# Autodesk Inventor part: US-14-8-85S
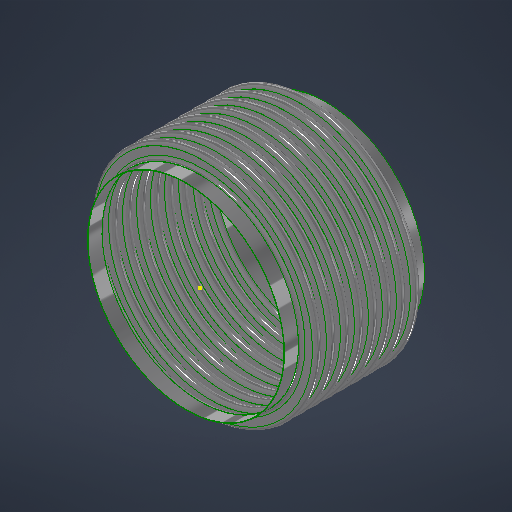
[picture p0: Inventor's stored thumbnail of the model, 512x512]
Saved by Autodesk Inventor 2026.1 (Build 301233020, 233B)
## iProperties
Category: 20 GA (0.036 THICK)
RuleStatus: InUse
Created: 2026-07
Part Number: US-14-8-85S
Project: =STOCK BELLOWS: <Stock Number><SFILL>
Material: ASTM A240-304
Description: =STOCK BELLOWS: <Stock Number>, <SID_> I.D., <SOD_> O.D., <SPLY_> PLY, <Category>, <SNET_CONS> CONS.<PITCH_><STANGENT_> TANGENT<SFILL>
Document SubType Name: Sheet Metal
Designer: LC
Stock Number: U.S-I4-8-85S
Surface Area: 659.127 cm^2
Volume: 56.61 cm^3
Sheet Metal Rule: Default
Appearance: STAINLESS STEEL
NET_TUBE: 3.428
COUNTER: 1.500
PBAR: 1.214
PSET: 5.356
PLY: 2
CONS: 2
THK: 0.036
ID: 4.500
OD: 5.500
CONS_: 2
TANGENT: 0.500
PITCH: 0.375
BELLOWS_UPSET: 0.000
NET_CONS: 2
S_CONS: 0
Description_Units: 0
ID_M: 114.30 mm
OD_M: 139.70 mm
THK_M: 0.91 mm
ID_U: 4.500 in
OD_U: 5.500 in
THK_U: 0.036 in
TANGENT2: 0.500
d79: 1.000
d82: 1.000
d83: 26.000
d84: 24.000
d80: 2.571
d81: 10
SID: 2.375
SCONS_: 8
SPITCH: 0.250
SBELLOWS_UPSET: 0.000
SNET_CONS: 8
SS_CONS: 0
SCONS: 8
d174: 8
d177: 0.018
d178: 2.375
d179: 3.000
d180: 0.375
d181: 1.000
d182: 0.000
d190: 8
d191: 1
d192: 1
d193: 8
d194: 0
PART_NUMBER: U.S-I4-8-85S
PRESSURE: 85
SIZE: 14.00
STANGENT_: 1.000
d214: 8
d217: 0.030
d218: 6.625
d219: 8.125
d220: 0.500
d221: 1.000
d222: 0.000
d230: 8
d231: 1
d232: 1
d233: 8
d234: 0
STANGENT: 4.000
SPLY_: 1
STHK_: 0.036
SID_: 14.000
SOD_: 16.125
SPITCH_: 1.000
STANGENT__: 1.000
SBELLOWS_UPSET_: 0.000
SDIFF_TAN: 1.000
TAN_TO_TAN: 0.750 in
d252: 2
d275: 2
d287: 0.050
d289: 0.500
d290: 0.000
d263: 2
d265: 1
d268: 2
d269: 0
d286: 2
d288: 1
d291: 2
d292: 0
SOD_NECK: 14 1/16
CFILL: .
SFILL: .
PITCH_: =, <SPITCH_> PITCH,
SREROLL: 0.750
MATTABLE: 20 GA (0.036 THICK)
MESH: ,
CSECT: 2
Author: LC
Keywords: 20 GA (0.036 THICK)
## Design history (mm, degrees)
sketch "Sketch2"
  geometry: L1 (0, -183.595)-(0, 600.956) reference; L2 (58.979, 0)-(57.15, 0); L3 (60.446, -1.467)-(66.554, -1.467); L4 (60.446, -3.296)-(66.554, -3.296); L5 (66.554, -8.058)-(60.446, -8.058); L6 (66.554, -6.229)-(60.446, -6.229); L7 (58.979, -9.525)-(57.15, -9.525); L8 (60.446, 0)-(60.446, -9.525); L9 (66.554, -4.762)-(69.85, -4.763); L10 (57.15, 0)-(57.15, -9.525); L11 (20.376, 102.841)-(20.376, 101.926); L12 (58.262, 488.877)-(58.262, 349.177); L13 (58.262, 479.352)-(58.262, 339.652); L14 (93.133, -58.817)-(93.133, -71.517); L15 (118.746, -66.401)-(118.746, -66.401); L16 (66.554, -6.229)-(66.554, -8.058); L17 (60.446, -6.229)-(60.446, -8.058); L18 (60.446, -7.144)-(66.554, -7.144); L19 (69.85, 0)-(69.85, -9.525); L20 (-66.554, -6.229)-(-66.554, -8.058); L21 (-66.554, -1.467)-(-60.446, -1.467); L22 (-66.554, -3.296)-(-60.446, -3.296); L23 (-60.446, -6.229)-(-66.554, -6.229); L24 (-66.554, -7.144)-(-60.446, -7.144); L25 (-60.446, -8.058)-(-66.554, -8.058); L26 (-60.446, -6.229)-(-60.446, -8.058); L27 (-57.15, -2.522)-(-57.15, -12.047); L28 (-60.446, -4.763)-(-57.15, -4.763); L29 (-66.554, 3.828)-(-66.554, -9.525); L30 (-68.021, 0)-(-69.85, 0); L31 (-69.85, 0)-(-69.85, -9.525); L32 (-68.021, -9.525)-(-69.85, -9.525); A1 r 1.467 centre (60.446, 0) between (58.979, 0) and (60.446, -1.467); A2 r 3.296 centre (60.446, 0) between (57.15, 0) and (60.446, -3.296); A3 r 3.296 centre (66.554, -4.762) between (66.554, -8.058) and (66.554, -1.467); A4 r 1.467 centre (66.554, -4.762) between (66.554, -6.229) and (66.554, -3.296); A5 r 1.467 centre (60.446, -9.525) between (60.446, -8.058) and (58.979, -9.525); A6 r 3.296 centre (60.446, -9.525) between (60.446, -6.229) and (57.15, -9.525); A7 r 2.381 centre (66.554, -4.762) between (66.554, -7.144) and (68.936, -4.762); A8 r 2.381 centre (60.446, -9.525) between (60.446, -7.144) and (58.064, -9.525); A9 r 1.467 centre (-66.554, -9.525) between (-66.554, -8.058) and (-68.021, -9.525); A10 r 1.467 centre (-60.446, -4.763) between (-60.446, -6.229) and (-60.446, -3.296); A11 r 2.381 centre (-60.446, -4.763) between (-60.446, -7.144) and (-58.064, -4.763); A12 r 3.296 centre (-60.446, -4.763) between (-60.446, -8.058) and (-60.446, -1.467); A13 r 2.381 centre (-66.554, -9.525) between (-66.554, -7.144) and (-68.936, -9.525); A14 r 3.296 centre (-66.554, -9.525) between (-66.554, -6.229) and (-69.85, -9.525); A15 r 1.467 centre (-66.554, 0) between (-68.021, 0) and (-66.554, -1.467); A16 r 3.296 centre (-66.554, 0) between (-69.85, 0) and (-66.554, -3.296); 10 further points
  constraints: 62 end point, 38 point on circle, 20 tangent, 16 centre point, 12 parallel, 9 midpoint, 7 vertical, 6 coincident, 6 concentric, 6 point on line, 4 equal radius, 4 perpendicular, 3 horizontal, 1 collinear, 1 horizontal alignment, 10 other
  dimensions: "THK" = 0.9144 distance of L11.start L11.end; "ID" = 114.3 distance of L11.end point (20.376, -12.374); "OD" = 139.7 distance of L12.start L12.end; "PITCH" = 9.525 distance of L12.start L13.start; "TANGENT" = 12.7 distance of L14.start L14.end; "BELLOWS_UPSET" = 0 distance of L15.start L15.end; "d43" = 114.3 diameter of L10 L1 (= ID); "d44" = 139.7 diameter of L9.end L1 (= OD); "d45" = 1.8288 distance between parallel lines of L5 L6 (computed from THK, PLY); "d46" = 3.29565 radius of A3 (computed from PITCH, THK, PLY); "UPSET_PITCH" = 9.525 distance of L2.end L7.end (derived); "SIDEWALL_ANGLE" = 0 deg angle of L3 L9 (derived); "CON_GAP" = 2.9337 distance of point (60.446, -6.229) point (60.446, -3.296) (derived); "TAN1" = 3.74046 dimension on A8 (derived); "TAN2" = 3.74046 dimension on A7 (derived); "LEG1" = 6.1087 distance of L18.start L18.end (derived); "d278" = 1.8288 distance between parallel lines of L25 L23 (derived); "d279" = 3.29565 radius of A12 (derived); "d280" = 9.525 distance of L30.end L31.end (derived); "d281" = 360 deg dimension on L21 L28 (derived); "d282" = 2.9337 distance of point (-66.554, -6.229) point (-66.554, -3.296) (derived); "d283" = 3.74046 dimension on A13 (derived); "d284" = 3.74046 dimension on A11 (derived); "d285" = 6.1087 distance of L24.start L24.end (derived); "d293" = 114.3 diameter of L27 L1 (derived); "d294" = 139.7 diameter of L31 L1 (derived)
  node "Sketch Rectangular Pattern1" dims "d31" = 25.4, "ID" = 114.3
  node "Sketch Rectangular Pattern2" dims "d39" = 25.4, "PITCH" = 9.525
revolve "CONS" stored, may be unused: angle "d48" = 90 deg
node "BELLOW MIDPLANE"
pattern_linear "Rectangular Pattern2" dims "d52" = 9.525 (= UPSET_PITCH)
sketch "Sketch5"
  geometry: C1 r 58.979 at (0, 0) reference; C2 r 57.15 at (0, 0) reference
extrude "TANGENT" new body sketch "Sketch5" distance "d53" = 12.7 (= TANGENT); taper "d54" = 0 deg
revolve "SAMETAN" stored, may be unused: angle "d65" = 90 deg
revolve "DIFFTAN" stored, may be unused: angle "d70" = 90 deg
sketch "Sketch9"
  geometry: L1 (58.391, 0)-(-58.391, 0) reference; L2 (0, -17.78)-(0, 17.78) reference; L3 (41.708, 0)-(-41.708, 0); L4 (41.708, -11.906)-(41.708, 11.906); L5 (29.008, -11.906)-(29.008, 11.906); L6 (15.418, 11.906)-(15.418, -11.906); L7 (-29.008, -11.906)-(-29.008, 11.906); L8 (-41.708, -11.906)-(-41.708, 11.906); L9 (40.914, -11.906)-(40.914, 11.906); L10 (41.708, -11.906)-(40.914, -11.906); L11 (41.708, 11.906)-(40.914, 11.906); L12 (15.815, 11.906)-(15.022, 11.906); L13 (15.022, 11.906)-(15.022, -11.906); L14 (15.022, -11.906)-(15.815, -11.906); L15 (15.815, -11.906)-(15.815, 11.906); L16 (-15.815, 11.906)-(-15.815, -11.906); L17 (-15.418, 11.906)-(-15.418, -11.906); L18 (-15.815, -11.906)-(-15.022, -11.906); L19 (-15.022, -11.906)-(-15.022, 11.906); L20 (-15.022, 11.906)-(-15.815, 11.906); L21 (-41.708, -11.906)-(-40.914, -11.906); L22 (-40.914, -11.906)-(-40.914, 11.906); L23 (-40.914, 11.906)-(-41.708, 11.906); L24 (-41.708, 11.906)-(-41.708, -11.906); L25 (41.708, -0.397)-(-41.708, -0.397); L26 (-41.708, -0.397)-(-41.708, 0.397); L27 (-41.708, 0.397)-(41.708, 0.397); L28 (41.708, 0.397)-(41.708, -0.397); L29 (-41.708, 11.906)-(41.708, 11.906); L30 (41.708, 11.906)-(41.708, 12.7); L31 (41.708, 12.7)-(-41.708, 12.7); L32 (-41.708, 12.7)-(-41.708, 11.906); L33 (41.708, -11.906)-(-41.708, -11.906); L34 (-41.708, -11.906)-(-41.708, -12.7); L35 (-41.708, -12.7)-(41.708, -12.7); L36 (41.708, -12.7)-(41.708, -11.906); 30 further points
  constraints: 68 end point, 13 midpoint, 13 parallel, 8 horizontal, 7 perpendicular, 6 equal length, 3 point on line, 2 vertical, 14 other
  dimensions: "d115" = 23.8125 distance of L4.start L4.end (derived); "d116" = 12.7 distance between parallel lines of L4 L5 (derived); "d117" = 13.58962 distance between parallel lines of L5 L6 (derived); "d125" = 44.42645 distance between parallel lines of L7 L6 (derived); "d127" = 12.7 distance between parallel lines of L8 L7 (derived); "d128" = 26.28962 distance between parallel lines of L6 L4 (derived); "d130" = 83.41607 distance between parallel lines of L8 L4 (derived); "RULER_THK" = 0.79375 distance between parallel lines of L4 L9; "d135" = 0.79375 distance of L13.end L14.end (derived); "d138" = 30.83684 distance of L13.end L16.end (derived); "d143" = 0.79375 distance of L22.end L8.end (derived); "d144" = 0.79375 distance between parallel lines of L27 L25 (derived)
extrude "RULER" join sketch "Sketch9" distance "d149" = 0.79375 (derived); taper "d150" = 0 deg
extrude "BARS" join sketch "Sketch9" distance "d151" = 0.79375 (derived); taper "d152" = 0 deg
pattern_linear "Rectangular Pattern4" dims "d155" = 30.83684 (derived)
sketch "Sketch13"
  geometry: L1 (93.149, -52.467)-(93.149, -77.867); L2 (178.714, 0)-(177.8, 0); L3 (178.714, -25.4)-(177.8, -25.4); L4 (197.98, -19.507)-(184.607, -19.507); L5 (197.98, -18.593)-(184.607, -18.593); L6 (197.98, -12.7)-(204.788, -12.7); L7 (184.607, -5.893)-(197.98, -5.893); L8 (184.607, 0)-(184.607, -25.4); L9 (177.8, 0)-(177.8, -25.4); L10 (58.254, -257.248)-(58.254, -666.823); L11 (58.254, -282.648)-(58.254, -692.223); L12 (58.254, -333.448)-(58.254, -743.023); L13 (58.254, -358.848)-(58.254, -768.423); L14 (58.254, -384.248)-(58.254, -793.823); L15 (58.254, -409.648)-(58.254, -819.223); L16 (58.254, -435.048)-(58.254, -844.623); L17 (58.254, -308.048)-(58.254, -717.623); L18 (20.376, 102.841)-(20.376, 101.926); L19 (184.607, -6.807)-(197.98, -6.807); L20 (0, -1008.715)-(0, 288.1) reference; L21 (-37.783, 0)-(226.695, 0) reference; A1 r 5.893 centre (184.607, 0) between (178.714, 0) and (184.607, -5.893); A2 r 5.893 centre (184.607, -25.4) between (184.607, -19.507) and (178.714, -25.4); A3 r 6.807 centre (184.607, -25.4) between (184.607, -18.593) and (177.8, -25.4); A4 r 5.893 centre (197.98, -12.7) between (197.98, -18.593) and (197.98, -6.807); A5 r 6.807 centre (197.98, -12.7) between (197.98, -19.507) and (197.98, -5.893); A6 r 6.807 centre (184.607, 0) between (177.8, 0) and (184.607, -6.807); 6 further points; 1 other entity
  constraints: 38 end point, 15 point on circle, 9 tangent, 6 centre point, 6 parallel, 5 vertical alignment, 4 point on line, 4 vertical, 3 coincident, 3 concentric, 2 collinear, 2 equal radius, 1 horizontal, 1 perpendicular, 23 other
  dimensions: "SBELLOWS_UPSET_" = 0 distance of point (118.762, -66.401) point (118.762, -66.401); "STOTAL_THK_BELLOW__" = 0.9144 distance between parallel lines of L4 L5 (derived); "d224" = 6.8072 radius of A5 (derived); "d225" = 25.4 distance of L2.end L3.end (derived); "SSIDEWALL_ANGLE_" = 0 deg angle of L7 L6 (derived); "SSCON_GAP_" = 11.7856 distance of point (184.607, -18.593) point (184.607, -6.807) (derived); "d235" = 355.6 diameter of L9 L20 (derived); "d236" = 409.575 diameter of L6.end L20 (derived)
  node "Sketch Rectangular Pattern4" dims "d228" = 25.4
  node "Sketch Rectangular Pattern5" dims "d229" = 25.4
revolve "SBELLOW" stored, may be unused: angle "d197" = 90 deg
pattern_linear "Rectangular Pattern5" dims "d204" = 25.4 (derived)
revolve "STANGENT" stored, may be unused: angle "d240" = 90 deg
revolve "SSAMETAN" stored, may be unused: angle "d241" = 90 deg
revolve "SDIFFTAN" stored, may be unused: angle "d246" = 90 deg
revolve "INVCON" stored, may be unused: angle "d295" = 90 deg
pattern_linear "Rectangular Pattern6" dims "d298" = 9.525 (derived)
revolve "INVTANGENT" stored, may be unused: angle "d302" = 90 deg
revolve "INVSAMETAN" stored, may be unused: angle "d307" = 90 deg
revolve "INVDIFFTAN" stored, may be unused: angle "d312" = 90 deg
sketch "ID BELLOW MOUNT CALC"
  geometry: L1 (44.45, 0)-(38.1, 0); L2 (38.1, 0)-(38.1, 12.7); L3 (38.1, 12.7)-(44.45, 12.7); L4 (44.45, 12.7)-(44.45, 0); L5 (36.513, 12.7)-(34.684, 12.7); L6 (34.684, 12.7)-(34.684, 0); L7 (34.684, 0)-(36.513, 0); L8 (36.513, 0)-(36.513, 12.7); L9 (0, -2.54)-(0, 15.24) reference; L10 (-8.89, 0)-(53.34, 0) reference; 1 further point
  constraints: 16 end point, 5 parallel, 2 collinear, 2 horizontal, 2 perpendicular
  dimensions: "d314" = 12.7 distance of L5.end L6.end (derived); "d315" = 1.8288 distance of L5.start L5.end (derived); "IG" = 1.5875 distance between parallel lines of L2 L8; "PIPE_OD" = 88.9 diameter of L4 L9; "PIPE_WALL" = 6.35 distance of L2.end L3.end; "ID_MT_BELLOW" = 69.3674 diameter of L6 L9 (derived)
revolve "CFILL" stored, may be unused: angle "d320" = 90 deg
pattern_linear "Rectangular Pattern7" dims "d323" = 9.525 (derived)
revolve "SFILL" stored, may be unused: angle "d324" = 90 deg
pattern_linear "Rectangular Pattern8" dims "d327" = 25.4 (derived)
node "STOCK BELLOW MIDPLANE"
sketch "Sketch21"
  geometry: L1 (0, -100.013)-(0, 100.013) reference; L2 (-100.013, 0)-(100.013, 0) reference; L3 (-0.099, 71.437)-(0.099, 71.437); L4 (0.099, 71.437)-(0.099, 55.562); L5 (0.099, 55.562)-(-0.099, 55.562); L6 (-0.099, 55.562)-(-0.099, 71.437); C1 r 55.562 at (0, 0); C2 r 71.437 at (0, 0); 3 further points
  constraints: 8 end point, 2 centre point, 2 coincident, 2 parallel, 2 tangent, 1 horizontal, 1 perpendicular, 1 other
  dimensions: "d329" = 111.125 diameter of C1 (derived); "d330" = 142.875 diameter of C2 (derived); "d331" = 0.19844 distance of L3.start L3.end
extrude "CLAMSHELL" cut sketch "Sketch21" extent not by distance; stored distance "d332" = 0; taper "d333" = 0 deg
pattern_circular "Circular Pattern1" dims angle "d335" = 180 deg (derived)
node "BELLOW"
sketch "Sketch6"
  geometry: L1 (-19.05, 58.979)-(-6.35, 58.979); L2 (-6.35, 58.979)-(-6.35, 57.15); L3 (-6.35, 57.15)-(-19.05, 57.15); L4 (-19.05, 57.15)-(-19.05, 58.979); L5 (2.54, 0)-(-59.69, 0) reference; L6 (-38.1, -108.388)-(-38.1, 156.601) reference; 1 further point
  constraints: 8 end point, 2 parallel, 1 horizontal, 1 perpendicular
  dimensions: "d61" = 12.7 distance of L2.end L3.end (derived); "d62" = 1.8288 distance of L1.end L2.end (derived); "d63" = 114.3 diameter of L3 L5 (derived); "d64" = 19.05 distance between parallel lines of L4 L6 (derived)
sketch "Sketch12"
  geometry: 1 further point
sketch "Sketch14"
  geometry: L1 (-25.4, 178.714)-(0, 178.714); L2 (0, 178.714)-(0, 177.8); L3 (0, 177.8)-(-25.4, 177.8); L4 (-25.4, 177.8)-(-25.4, 178.714); L5 (5.08, 0)-(-30.48, 0) reference; L6 (0, -32.568)-(0, 195.407) reference; 1 further point
  constraints: 8 end point, 2 parallel, 1 collinear, 1 horizontal, 1 perpendicular
  dimensions: "d237" = 0.9144 distance of L3.end L1.start (derived); "d238" = 355.6 diameter of L3 L5 (derived); "d239" = 25.4 distance of L1.start L1.end (derived); "SOD_NECK" = 357.4288 diameter of L1 L5 (derived)
sketch "Sketch15"
  geometry: L1 (-32.568, 0)-(195.407, 0) reference; L2 (177.8, -203.2)-(178.714, -203.2); L3 (178.714, -203.2)-(178.714, -228.6); L4 (178.714, -228.6)-(177.8, -228.6); L5 (177.8, -228.6)-(177.8, -203.2); L6 (0, -276.86)-(0, 60.96) reference; 1 further point
  constraints: 8 end point, 2 parallel, 1 horizontal, 1 perpendicular
  dimensions: "d205" = 25.4 distance of L4.end L2.start (derived); "d206" = 0.9144 distance of L3.end L4.end (derived); "d207" = 355.6 diameter of L5 L6 (derived); "d208" = 203.2 distance between parallel lines of L1 L2 (derived)
node "TANGENT_"
node "SAME_TAN"
sketch "Sketch8"
  geometry: L1 (58.979, -19.05)-(57.15, -19.05); L2 (57.15, -19.05)-(57.15, -31.75); L3 (57.15, -31.75)-(58.979, -31.75); L4 (58.979, -31.75)-(58.979, -19.05); L5 (0, -40.64)-(0, 21.59) reference; L6 (-108.388, 0)-(156.601, 0) reference; 1 further point
  constraints: 8 end point, 2 parallel, 1 horizontal, 1 perpendicular
  dimensions: "d66" = 114.3 diameter of L2 L5 (derived); "TOTAL_THK_BELLOW" = 1.8288 distance of L2.end L3.end (derived); "d68" = 19.05 distance between parallel lines of L1 L6 (derived); "d69" = 12.7 distance of L1.end L2.end (derived)
node "DIFF_TAN"
node "Sketch Rectangular Pattern3" dims "d138" = 30.83684 (derived), "d141" = 25.4
node "SBELLOW_"
node "STANGENT_"
node "SSAME_TAN"
sketch "Sketch16"
  geometry: L1 (178.714, -203.2)-(177.8, -203.2); L2 (177.8, -203.2)-(177.8, -228.6); L3 (177.8, -228.6)-(178.714, -228.6); L4 (178.714, -228.6)-(178.714, -203.2); L5 (0, -276.86)-(0, 60.96) reference; L6 (-32.568, 0)-(195.407, 0) reference; 1 further point
  constraints: 8 end point, 2 parallel, 1 horizontal, 1 perpendicular
  dimensions: "SDIFF_TAN" = 25.4 distance of L3.end L1.start; "d243" = 0.9144 distance of L2.end L3.end (derived); "d244" = 203.2 distance between parallel lines of L1 L6 (derived); "d245" = 355.6 diameter of L2 L5 (derived)
node "SDIFF_TAN"
body "Solid15"
sketch "Sketch17"
  geometry: L1 (69.85, 12.7)-(68.021, 12.7); L2 (68.021, 12.7)-(68.021, 0); L3 (68.021, 0)-(69.85, 0); L4 (69.85, 0)-(69.85, 12.7); L5 (0, -2.54)-(0, 15.24) reference; L6 (-13.97, 0)-(83.82, 0) reference; 2 further points
  constraints: 8 end point, 2 parallel, 1 horizontal, 1 midpoint, 1 perpendicular, 1 point on line
  dimensions: "INVTANGENT" = 12.7 distance of L3.end L1.start (derived); "d300" = 1.8288 distance of L1.start L1.end (derived); "d301" = 139.7 diameter of L4 L5 (derived)
body "Solid16"
sketch "Sketch18"
  geometry: L1 (69.85, -19.05)-(68.021, -19.05); L2 (68.021, -19.05)-(68.021, -31.75); L3 (68.021, -31.75)-(69.85, -31.75); L4 (69.85, -31.75)-(69.85, -19.05); L5 (-13.97, 0)-(83.82, 0) reference; L6 (0, -40.64)-(0, 21.59) reference; 1 further point
  constraints: 8 end point, 2 parallel, 1 horizontal, 1 perpendicular
  dimensions: "d303" = 19.05 distance between parallel lines of L1 L5 (derived); "d304" = 12.7 distance of L3.end L1.start (derived); "d305" = 1.8288 distance of L2.end L3.end (derived); "d306" = 139.7 diameter of L4 L6 (derived)
body "Solid17"
sketch "Sketch19"
  geometry: L1 (69.85, -19.05)-(68.021, -19.05); L2 (68.021, -19.05)-(68.021, -31.75); L3 (68.021, -31.75)-(69.85, -31.75); L4 (69.85, -31.75)-(69.85, -19.05); L5 (0, -40.64)-(0, 21.59) reference; L6 (-13.97, 0)-(83.82, 0) reference; 1 further point
  constraints: 8 end point, 2 parallel, 1 horizontal, 1 perpendicular
  dimensions: "d308" = 12.7 distance of L1.end L2.end (derived); "d309" = 139.7 diameter of L4 L5 (derived); "d310" = 1.8288 distance of L2.end L3.end (derived); "d311" = 19.05 distance between parallel lines of L1 L6 (derived)
body "Solid18"
body "Solid19"
body "Solid20"
other parameters: "BMPL" = -101.6, "PSET" = 136.0424 (computed from OD, THK, PLY) [user parameter], "PBAR" = 30.83684 (= 0.570796 x PITCH + OD - ID) [user parameter; used in 1 equation term], "COUNTER" = 15 [user parameter], "NET_TUBE" = 87.07367 (computed from CONS_, PBAR, TANGENT) [user parameter], "S_CONS" = 0 [user parameter; used in 1 equation term], "ID_M" = 114.3 (= ID) [user parameter], "OD_M" = 139.7 (= OD) [user parameter], "THK_M" = 0.9144 (= THK) [user parameter], "ID_U" = 114.3 (= ID) [user parameter], "OD_U" = 139.7 (= OD) [user parameter], "THK_U" = 0.9144 (= THK) [user parameter], "D_UNITS" = 0 [user parameter], "TANGENT2" = 12.7 [user parameter], "TAN_TO_TAN" = 19.05 [user parameter], "OD_NECK" = 117.9576 [user parameter], "d79" = 25.4, "d80" = 65.29823 [user parameter], "d82" = 25.4, "d83" = 660.4, "d84" = 609.6, "sa_0" = 4, "FRAME_THK" = 0.79375 [user parameter], "CON_FLAT" = 13.58962 [user parameter], "SID" = 60.325 [user parameter], "SPITCH" = 6.35 [user parameter], "STANGENT_" = 25.4 [user parameter], "SBELLOWS_UPSET" = 0 [user parameter], "SS_CONS" = 0 [user parameter], "STAN_TO_TAN_" = 203.2 [user parameter], "d100" = 0.9144 [user parameter], "d191" = 25.4 [user parameter], "d194" = 0 [user parameter], "STANGENT" = 101.6 [user parameter], "d234" = 0 [user parameter], "SUPSET_PITCH_" = 25.4 [user parameter], "d269" = 0 [user parameter], "d287" = 1.27, "d289" = 12.7, "d290" = 0, "d292" = 0 [user parameter], "Thickness" = 3.048 (derived), "KFactor" = 4.4, "BendRadius" = 3.048 (derived), "BendReliefWidth" = 3.048 (derived), "BendReliefDepth" = 1.524 (derived), "CornerReliefSize" = 12.192 (derived), "SeamGap" = 0.00508, "MinimumRemnant" = 6.096 (derived), "TransitionRadius" = 3.048 (derived), "JacobiRadiusSize" = 3.048 (derived), "GapSize" = 3.048 (derived), "SREROLL" = 19.05 [user parameter], "CUR_STK_PITCH" = 25.4 [user parameter], "d328" = -101.6 (derived), "CSECTDEG" = 180 deg [user parameter]
